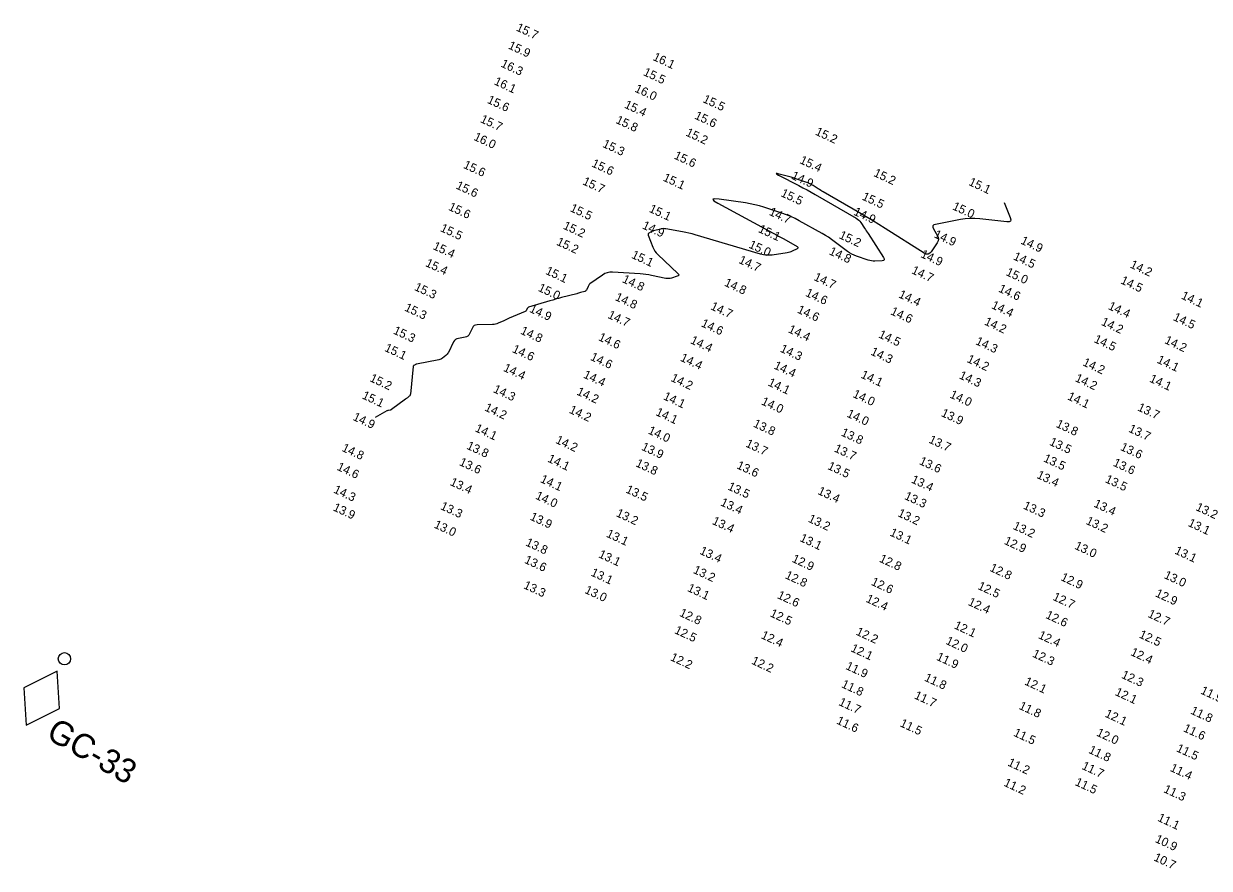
# Model space of a CAD drawing. Extents: x 988130 to 1132882, y 654656 to 841453.
# Drawn here: x 1099611 to 1100298, y 701622 to 702111 of the extents above; entities that cross this region are included whole.
import ezdxf

# ---------------------------------------------------------------- set-up
doc = ezdxf.new("R2010")
doc.units = 0
for name, color, linetype in [('V-CHAN-NAID', 7, 'Continuous'), ('V-TOPO-MAJR', 7, 'Continuous'), ('V-TOPO-SOUN', 7, 'Continuous')]:
    doc.layers.add(name, color=color, linetype=linetype)

msp = doc.modelspace()

# ---------------------------------------------------------------- linework, layer by layer
at = {"layer": 'V-CHAN-NAID'}
msp.add_lwpolyline([(1099630.65, 701736.12), (1099611.26, 701726.53), (1099612.65, 701704.94), (1099632.04, 701714.53)], close=True, dxfattribs=at)
msp.add_lwpolyline([(1099630.65, 701736.12), (1099611.26, 701726.53), (1099612.65, 701704.94), (1099632.04, 701714.53)], close=True, dxfattribs=at)
msp.add_circle((1099634.85, 701743.39), 3.6, dxfattribs=at)
msp.add_circle((1099634.85, 701743.39), 3.6, dxfattribs=at)
at = {"layer": 'V-TOPO-MAJR'}
msp.add_lwpolyline([(1100179.31, 702007.71), (1100182.82, 701998.97), (1100183.14, 701997.72), (1100182.92, 701996.87), (1100182.17, 701996.44), (1100180.88, 701996.42), (1100165.17, 701998.26), (1100162.35, 701998.48), (1100159.54, 701998.48), (1100156.73, 701998.26), (1100153.94, 701997.83), (1100139.5, 701995), (1100138.56, 701994.67), (1100138.06, 701994.15), (1100137.99, 701993.42), (1100138.36, 701992.5), (1100140.72, 701988.4), (1100141.15, 701987.38), (1100141.27, 701986.38), (1100141.08, 701985.38), (1100140.58, 701984.4), (1100137.07, 701979.19), (1100136.21, 701978.24), (1100135.25, 701977.78), (1100134.19, 701977.81), (1100133.02, 701978.34), (1100110.39, 701992.63), (1100106.71, 701994.93), (1100103.01, 701997.2), (1100099.29, 701999.43), (1100095.54, 702001.62), (1100074.52, 702013.8), (1100073.76, 702014.24), (1100073.02, 702014.69), (1100072.28, 702015.15), (1100071.54, 702015.63), (1100068.61, 702017.53), (1100067.87, 702017.99), (1100067.1, 702018.39), (1100066.31, 702018.76), (1100065.5, 702019.07), (1100060.42, 702020.86), (1100059.29, 702021.25), (1100058.16, 702021.61), (1100057.02, 702021.96), (1100055.87, 702022.28), (1100048.89, 702024.17), (1100047.71, 702024.45), (1100047.28, 702024.43), (1100047.59, 702024.13), (1100048.64, 702023.54), (1100060.32, 702017.5), (1100062.73, 702016.24), (1100065.13, 702014.94), (1100067.51, 702013.62), (1100069.88, 702012.27), (1100093.57, 701998.55), (1100094.35, 701998.04), (1100095.06, 701997.44), (1100095.7, 701996.77), (1100096.26, 701996.02), (1100098.37, 701992.86), (1100098.9, 701992.07), (1100099.42, 701991.27), (1100099.94, 701990.48), (1100100.46, 701989.68), (1100109.49, 701975.8), (1100109.85, 701975.05), (1100109.81, 701974.49), (1100109.39, 701974.13), (1100108.56, 701973.98), (1100104.48, 701973.75), (1100103.46, 701973.74), (1100102.46, 701973.83), (1100101.47, 701974.01), (1100100.5, 701974.29), (1100093.8, 701976.57), (1100092.39, 701977.11), (1100091.03, 701977.76), (1100089.74, 701978.52), (1100088.49, 701979.38), (1100080.92, 701985.11), (1100079.23, 701986.34), (1100077.51, 701987.51), (1100075.74, 701988.62), (1100073.94, 701989.67), (1100060.61, 701997.11), (1100058.18, 701998.39), (1100055.7, 701999.55), (1100053.17, 702000.59), (1100050.58, 702001.5), (1100040.13, 702004.91), (1100037.51, 702005.7), (1100034.85, 702006.38), (1100032.17, 702006.95), (1100029.47, 702007.4), (1100014.11, 702009.61), (1100011.46, 702009.84), (1100010.45, 702009.53), (1100011.08, 702008.67), (1100013.34, 702007.28), (1100045.54, 701989.91), (1100047.07, 701989.09), (1100048.59, 701988.25), (1100050.11, 701987.41), (1100051.62, 701986.57), (1100059.35, 701982.23), (1100059.86, 701981.86), (1100060.02, 701981.5), (1100059.83, 701981.15), (1100059.3, 701980.81), (1100056.49, 701979.48), (1100055.78, 701979.18), (1100055.05, 701978.93), (1100054.31, 701978.73), (1100053.55, 701978.58), (1100044.9, 701977.26), (1100043.21, 701977.09), (1100041.54, 701977.12), (1100039.87, 701977.32), (1100038.22, 701977.72), (1100000.37, 701989.01), (1099998.55, 701989.52), (1099996.71, 701989.98), (1099994.86, 701990.39), (1099992.99, 701990.74), (1099983.38, 701992.41), (1099982.58, 701992.51), (1099981.78, 701992.52), (1099980.99, 701992.44), (1099980.2, 701992.28), (1099976.22, 701991.26), (1099975.86, 701991.15), (1099975.5, 701991.02), (1099975.15, 701990.87), (1099974.82, 701990.69), (1099973.49, 701989.92), (1099973.22, 701989.71), (1099973.06, 701989.46), (1099973.02, 701989.16), (1099973.1, 701988.83), (1099975.71, 701981.9), (1099976.26, 701980.67), (1099976.93, 701979.52), (1099977.73, 701978.46), (1099978.66, 701977.49), (1099990.24, 701966.62), (1099990.68, 701966.08), (1099990.77, 701965.61), (1099990.5, 701965.23), (1099989.86, 701964.93), (1099986.63, 701963.89), (1099985.81, 701963.69), (1099985, 701963.59), (1099984.17, 701963.6), (1099983.34, 701963.72), (1099975.08, 701965.44), (1099973.43, 701965.75), (1099971.76, 701966), (1099970.09, 701966.2), (1099968.41, 701966.34), (1099952.43, 701967.35), (1099950.84, 701967.32), (1099949.33, 701967.03), (1099947.89, 701966.47), (1099946.52, 701965.65), (1099939.33, 701960.47), (1099938.97, 701960.18), (1099938.67, 701959.85), (1099938.42, 701959.48), (1099938.22, 701959.07), (1099937.53, 701957.33), (1099937.32, 701956.94), (1099937.04, 701956.62), (1099936.7, 701956.37), (1099936.29, 701956.2), (1099933.86, 701955.48), (1099933.31, 701955.32), (1099932.76, 701955.16), (1099932.2, 701955.01), (1099931.64, 701954.87), (1099922.77, 701952.56), (1099921.11, 701952.12), (1099919.45, 701951.67), (1099917.8, 701951.19), (1099916.15, 701950.71), (1099903.74, 701946.96), (1099903.5, 701946.86), (1099903.3, 701946.72), (1099903.14, 701946.54), (1099903.01, 701946.32), (1099902.58, 701945.33), (1099902.46, 701945.1), (1099902.3, 701944.91), (1099902.1, 701944.75), (1099901.87, 701944.63), (1099892.48, 701940.62), (1099891.69, 701940.27), (1099890.9, 701939.93), (1099890.12, 701939.57), (1099889.34, 701939.21), (1099886.22, 701937.74), (1099885.43, 701937.42), (1099884.62, 701937.19), (1099883.79, 701937.04), (1099882.94, 701936.98), (1099873.96, 701936.83), (1099873.08, 701936.71), (1099872.34, 701936.38), (1099871.73, 701935.84), (1099871.26, 701935.09), (1099869.63, 701931.68), (1099869.16, 701930.92), (1099868.55, 701930.32), (1099867.82, 701929.9), (1099866.95, 701929.65), (1099863.08, 701928.96), (1099862.19, 701928.7), (1099861.43, 701928.27), (1099860.8, 701927.66), (1099860.3, 701926.88), (1099857.33, 701920.86), (1099857.03, 701920.34), (1099856.68, 701919.85), (1099856.27, 701919.42), (1099855.81, 701919.02), (1099853.87, 701917.54), (1099853.37, 701917.2), (1099852.84, 701916.92), (1099852.28, 701916.71), (1099851.7, 701916.56), (1099838.77, 701914.02), (1099838.57, 701913.97), (1099838.38, 701913.91), (1099838.19, 701913.83), (1099838.01, 701913.73), (1099837.29, 701913.31), (1099837.13, 701913.19), (1099837.01, 701913.04), (1099836.93, 701912.88), (1099836.89, 701912.68), (1099835.3, 701896.72), (1099835.23, 701896.37), (1099835.1, 701896.06), (1099834.92, 701895.77), (1099834.67, 701895.52), (1099833.55, 701894.58), (1099833.27, 701894.35), (1099832.99, 701894.12), (1099832.7, 701893.9), (1099832.41, 701893.68), (1099824.4, 701887.78), (1099824.2, 701887.65), (1099823.99, 701887.55), (1099823.77, 701887.47), (1099823.54, 701887.41), (1099822.6, 701887.24), (1099822.37, 701887.19), (1099822.14, 701887.12), (1099821.92, 701887.03), (1099821.71, 701886.93), (1099814.79, 701883.18)], dxfattribs=at)

# ---------------------------------------------------------------- texts
at = {"layer": 'V-CHAN-NAID'}
msp.add_text('GC-33', height=14, rotation=330, dxfattribs=at).set_placement((1099623.6, 701697.72))
at = {"layer": 'V-TOPO-SOUN'}
for s, p in [('15.7 ', (1099896.18, 702107.43)), ('15.9 ', (1099891.58, 702097.01)), ('16.3 ', (1099887.32, 702086.51)), ('16.1 ', (1099975.39, 702090.35)), ('15.5 ', (1099969.84, 702081.58)), ('16.1 ', (1099883.38, 702076.26)), ('16.0 ', (1099964.86, 702072.03)), ('15.6 ', (1099879.39, 702065.54)), ('15.5 ', (1100004.32, 702065.94)), ('15.4 ', (1099958.88, 702062.73)), ('15.7 ', (1099875.41, 702054.35)), ('15.8 ', (1099953.89, 702053.88)), ('15.6 ', (1099999.55, 702056.39)), ('16.0 ', (1099871.6, 702044.08)), ('15.2 ', (1099994.44, 702046.58)), ('15.2 ', (1100069.49, 702047.1)), ('15.3 ', (1099946.22, 702040.03)), ('15.6 ', (1099987.63, 702033.27)), ('15.4 ', (1100060.44, 702030.61)), ('15.6 ', (1099865.57, 702027.87)), ('15.6 ', (1099939.92, 702028.7)), ('15.2 ', (1100103.28, 702023.15)), ('15.6 ', (1099861.29, 702015.91)), ('15.7 ', (1099934.68, 702018.32)), ('15.1 ', (1099981.25, 702020.49)), ('14.9 ', (1100055.61, 702021.62)), ('15.1 ', (1100158.35, 702017.95)), ('15.5 ', (1100049.49, 702011.47)), ('15.5 ', (1100096.56, 702009.51)), ('15.6 ', (1099856.94, 702003.55)), ('15.5 ', (1099927.39, 702002.79)), ('15.1 ', (1099973.18, 702002.43)), ('15.0 ', (1100148.95, 702003.85)), ('14.7 ', (1100042.69, 702000.68)), ('14.9 ', (1100091.67, 702000.74)), ('15.5 ', (1099852.23, 701991.25)), ('15.2 ', (1099923.39, 701992.65)), ('14.9 ', (1099969.23, 701992.81)), ('15.1 ', (1100036.47, 701990.7)), ('15.2 ', (1099919.55, 701983.31)), ('15.0 ', (1100030.94, 701981.67)), ('15.2 ', (1100083.23, 701987.14)), ('14.9 ', (1100138.28, 701987.64)), ('14.9 ', (1100188.5, 701984.02)), ('15.4 ', (1099847.93, 701980.81)), ('15.1 ', (1099962.98, 701975.75)), ('14.8 ', (1100077.47, 701977.81)), ('14.9 ', (1100130.55, 701976.17)), ('14.5 ', (1100184.2, 701974.85)), ('15.4 ', (1099843.62, 701970.97)), ('14.7 ', (1100025.12, 701972.8)), ('14.2 ', (1100251.87, 701970.13)), ('15.1 ', (1099913.17, 701966.46)), ('14.8 ', (1099957.66, 701961.66)), ('14.7 ', (1100068.64, 701962.9)), ('14.7 ', (1100125.24, 701966.84)), ('15.0 ', (1100179.93, 701965.74)), ('14.5 ', (1100246.37, 701960.98)), ('15.3 ', (1099837.21, 701957.12)), ('15.0 ', (1099908.87, 701956.63)), ('14.8 ', (1100016.78, 701959.65)), ('14.6 ', (1100175.62, 701956.19)), ('14.8 ', (1099953.49, 701951.28)), ('14.6 ', (1100063.78, 701953.75)), ('14.4 ', (1100117.77, 701952.85)), ('14.1 ', (1100281.48, 701952.16)), ('15.3 ', (1099831.51, 701945.19)), ('14.9 ', (1099903.84, 701944.47)), ('14.7 ', (1099949.25, 701940.96)), ('14.7 ', (1100008.81, 701945.97)), ('14.6 ', (1100059.01, 701944.05)), ('14.6 ', (1100113.09, 701943.05)), ('14.4 ', (1100171.53, 701946.6)), ('14.4 ', (1100239.2, 701946.09)), ('14.6 ', (1100003.36, 701936.1)), ('14.2 ', (1100167.44, 701937.12)), ('14.2 ', (1100235.13, 701936.95)), ('14.5 ', (1100276.84, 701939.68)), ('15.3 ', (1099824.94, 701931.91)), ('14.8 ', (1099898.68, 701931.82)), ('14.6 ', (1099943.81, 701928.07)), ('14.4 ', (1100053.78, 701932.64)), ('14.5 ', (1100106.13, 701929.66)), ('14.5 ', (1100230.97, 701926.94)), ('15.1 ', (1099819.92, 701921.86)), ('14.6 ', (1099893.89, 701921.2)), ('14.4 ', (1099997.12, 701926.3)), ('14.3 ', (1100049.12, 701921.42)), ('14.3 ', (1100101.55, 701919.72)), ('14.3 ', (1100162.35, 701925.74)), ('14.2 ', (1100271.88, 701926.34)), ('14.6 ', (1099939.17, 701916.65)), ('14.4 ', (1099991.28, 701916.16)), ('14.2 ', (1100157.38, 701915.41)), ('14.2 ', (1100224.43, 701913.5)), ('14.1 ', (1100267.47, 701915.01)), ('14.4 ', (1099888.76, 701910.27)), ('14.4 ', (1099935.12, 701906.38)), ('14.4 ', (1100045.48, 701911.66)), ('14.1 ', (1100095.87, 701906.35)), ('14.3 ', (1100152.81, 701905.97)), ('15.2 ', (1099811.34, 701904.32)), ('14.2 ', (1099985.77, 701904.45)), ('14.1 ', (1100042.07, 701901.81)), ('14.2 ', (1100220, 701904.34)), ('14.1 ', (1100263.1, 701904.03)), ('15.1 ', (1099806.9, 701894.33)), ('14.3 ', (1099882.9, 701897.95)), ('14.2 ', (1099931.24, 701896.56)), ('14.1 ', (1099981.42, 701893.84)), ('14.0 ', (1100091.2, 701895.15)), ('14.0 ', (1100147.42, 701894.86)), ('14.1 ', (1100215.59, 701893.75)), ('14.2 ', (1099877.92, 701887.34)), ('14.2 ', (1099926.89, 701886.01)), ('14.0 ', (1100038.22, 701890.87)), ('13.7 ', (1100256.19, 701887.39)), ('14.9 ', (1099801.55, 701881.89)), ('14.1 ', (1099977.02, 701884.66)), ('14.0 ', (1100087.74, 701883.75)), ('13.9 ', (1100142.41, 701884.13)), ('14.1 ', (1099872.32, 701875.3)), ('14.0 ', (1099972.59, 701874.02)), ('13.8 ', (1100033.53, 701878)), ('13.8 ', (1100084.41, 701872.86)), ('13.8 ', (1100208.94, 701877.83)), ('13.7 ', (1100251, 701875.04)), ('13.8 ', (1099867.46, 701865.18)), ('14.2 ', (1099919.02, 701868.55)), ('13.7 ', (1100029.13, 701866.44)), ('13.7 ', (1100135.23, 701868.73)), ('13.5 ', (1100205.14, 701867.44)), ('14.8 ', (1099795.16, 701863.93)), ('13.9 ', (1099968.78, 701864.57)), ('13.7 ', (1100080.43, 701863.6)), ('13.5 ', (1100201.68, 701857.86)), ('13.6 ', (1100246.27, 701864.48)), ('14.6 ', (1099792.32, 701852.98)), ('13.6 ', (1099863.2, 701855.73)), ('14.1 ', (1099914.4, 701857.69)), ('13.8 ', (1099965.4, 701855.05)), ('13.6 ', (1100023.94, 701853.85)), ('13.5 ', (1100076.64, 701853.42)), ('13.6 ', (1100129.71, 701856.28)), ('13.6 ', (1100242.02, 701855.34)), ('13.4 ', (1099857.88, 701844.14)), ('14.1 ', (1099910.17, 701845.87)), ('13.4 ', (1100125.08, 701845.62)), ('13.4 ', (1100197.82, 701848.26)), ('13.5 ', (1100237.43, 701845.8)), ('14.3 ', (1099790.37, 701839.77)), ('13.5 ', (1099959.67, 701839.86)), ('13.5 ', (1100018.74, 701841.59)), ('13.4 ', (1100070.91, 701838.96)), ('14.0 ', (1099907.33, 701836.24)), ('13.4 ', (1100014.58, 701832.4)), ('13.3 ', (1100121.14, 701836.04)), ('13.3 ', (1100189.96, 701830.54)), ('13.4 ', (1100230.84, 701831.65)), ('13.9 ', (1099790.08, 701829.46)), ('13.3 ', (1099852.28, 701830.2)), ('13.9 ', (1099904.19, 701824.12)), ('13.2 ', (1099954.06, 701826.13)), ('13.2 ', (1100117.24, 701826.13)), ('13.2 ', (1100289.9, 701829.64)), ('13.0 ', (1099848.57, 701819.52)), ('13.4 ', (1100009.75, 701821.6)), ('13.2 ', (1100065.36, 701822.9)), ('13.2 ', (1100184, 701818.75)), ('13.2 ', (1100226.29, 701821.65)), ('13.1 ', (1100285.45, 701820.47)), ('13.1 ', (1099948.42, 701814.22)), ('13.1 ', (1100060.52, 701811.72)), ('13.1 ', (1100112.68, 701814.93)), ('12.9 ', (1100178.88, 701810.08)), ('13.8 ', (1099901.64, 701809.18)), ('13.4 ', (1100002.5, 701804.31)), ('13.0 ', (1100219.74, 701807.22)), ('13.1 ', (1100277.7, 701804.48)), ('13.6 ', (1099900.95, 701799.11)), ('13.1 ', (1099943.89, 701802.32)), ('12.9 ', (1100055.95, 701799.71)), ('12.8 ', (1100106.58, 701799.75)), ('13.1 ', (1099939.44, 701791.75)), ('13.2 ', (1099998.72, 701793.24)), ('12.8 ', (1100052, 701790.18)), ('12.8 ', (1100170.54, 701794.46)), ('13.0 ', (1100271.55, 701790.25)), ('13.3 ', (1099900.45, 701784.39)), ('13.1 ', (1099995.39, 701782.78)), ('12.6 ', (1100101.85, 701786.37)), ('12.5 ', (1100163.65, 701783.93)), ('12.9 ', (1100211.7, 701789.04)), ('13.0 ', (1099935.9, 701781.66)), ('12.6 ', (1100047.48, 701778.63)), ('12.4 ', (1100098.81, 701776.52)), ('12.7 ', (1100207.08, 701777.67)), ('12.9 ', (1100266.51, 701779.67)), ('12.4 ', (1100158.01, 701774.71)), ('12.8 ', (1099990.75, 701768.39)), ('12.5 ', (1100043.26, 701768.11)), ('12.6 ', (1100202.93, 701767.15)), ('12.7 ', (1100262.15, 701767.76)), ('12.5 ', (1099987.9, 701758.36)), ('12.4 ', (1100038.05, 701755.44)), ('12.2 ', (1100093.06, 701757.49)), ('12.1 ', (1100149.9, 701761.13)), ('12.4 ', (1100198.72, 701755.48)), ('12.5 ', (1100257.07, 701755.86)), ('12.0 ', (1100145.06, 701752.16)), ('12.2 ', (1099985.49, 701742.68)), ('12.1 ', (1100090.04, 701747.87)), ('11.9 ', (1100139.65, 701742.93)), ('12.3 ', (1100195.28, 701744.74)), ('12.4 ', (1100252.18, 701745.66)), ('12.2 ', (1100032.51, 701740.65)), ('11.9 ', (1100087.11, 701737.59)), ('11.8 ', (1100132.7, 701730.87)), ('12.1 ', (1100190.72, 701728.64)), ('12.3 ', (1100246.85, 701732.49)), ('11.8 ', (1100084.63, 701727.06)), ('11.7 ', (1100126.84, 701720.58)), ('12.1 ', (1100243.16, 701722.52)), ('11.9 ', (1100292.71, 701723.4)), ('11.7 ', (1100083.05, 701716.72)), ('11.8 ', (1100187.49, 701714.5)), ('12.1 ', (1100237.31, 701709.97)), ('11.8 ', (1100286.92, 701711.75)), ('11.6 ', (1100081.77, 701705.98)), ('11.5 ', (1100118.54, 701704.44)), ('11.6 ', (1100282.71, 701701.55)), ('11.5 ', (1100184.33, 701698.94)), ('12.0 ', (1100232.41, 701699.01)), ('11.8 ', (1100227.86, 701689.02)), ('11.5 ', (1100278.7, 701689.95)), ('11.2 ', (1100180.94, 701681.69)), ('11.7 ', (1100223.91, 701679.71)), ('11.4 ', (1100275.06, 701678.56)), ('11.2 ', (1100178.69, 701669.99)), ('11.5 ', (1100219.97, 701670.37)), ('11.3 ', (1100271.29, 701666.25)), ('11.1 ', (1100267.79, 701649.7)), ('10.9 ', (1100266.38, 701637.38)), ('10.7 ', (1100265.58, 701626.73))]:
    msp.add_text(s, height=5, rotation=335, dxfattribs=at).set_placement(p)

doc.saveas('drawing.dxf')
